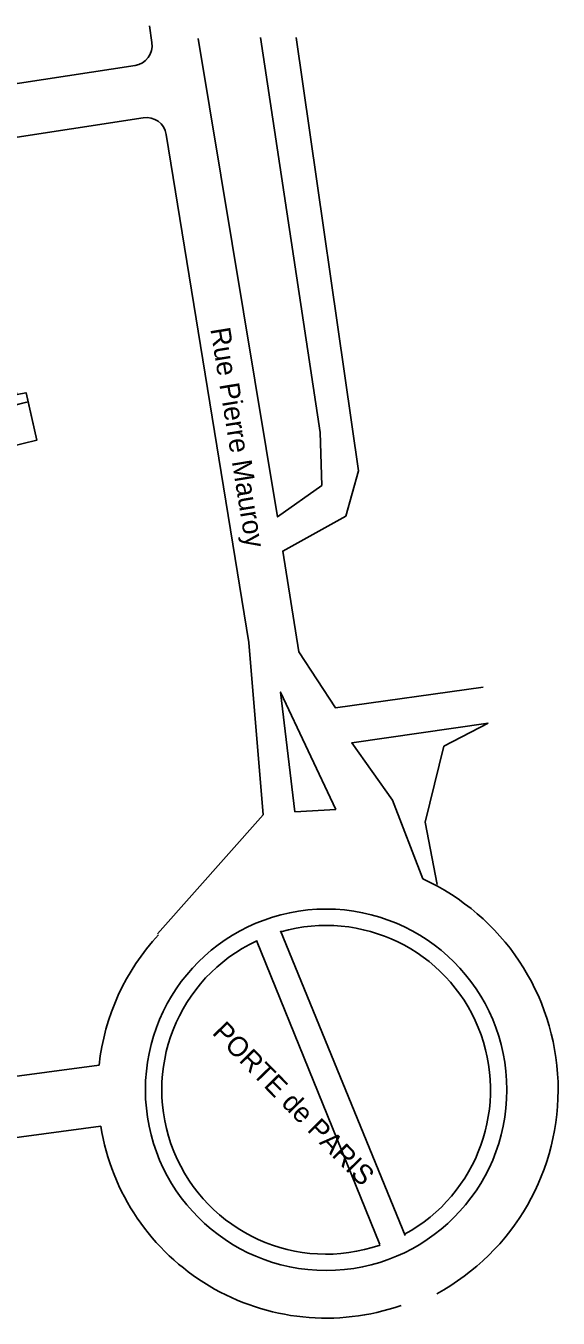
# Model space of a CAD drawing. Extents: x 704421 to 705059, y 7058908 to 7059523.
# Drawn here: x 704581.3 to 704661.8, y 7058918.9 to 7059114.3 of the extents above; entities that cross this region are included whole.
import ezdxf

# ---------------------------------------------------------------- set-up
doc = ezdxf.new("R2010")
doc.units = 0
for name, color, linetype in [('DH_HACHURE-MOTIF', 7, 'Continuous'), ('DH_TEXTE', 7, 'Continuous'), ('GO_MUR_EXTERIEUR', 7, 'Continuous'), ('IMM_LIMITE PHYSIQUE', 7, 'Continuous'), ('SID_POLYLIGNES_IMMEUBLE', 7, 'Continuous'), ('VOIRIE_ROUTE', 7, 'Continuous')]:
    doc.layers.add(name, color=color, linetype=linetype)

msp = doc.modelspace()

# ---------------------------------------------------------------- linework, layer by layer
at = {"layer": 'DH_HACHURE-MOTIF'}
msp.add_lwpolyline([(704564.85, 7059044.01), (704565.09, 7059042.95), (704579.84, 7059046.44), (704578.84, 7059050.66), (704582.98, 7059051.69), (704581.66, 7059057.48), (704581.22, 7059057.37), (704557.88, 7059051.53), (704560.06, 7059042.8), (704564.85, 7059044.01)], dxfattribs=at)
at = {"layer": 'GO_MUR_EXTERIEUR'}
for p, q in [((704557.88, 7059051.53), (704581.66, 7059057.48)), ((704581.66, 7059057.48), (704582.98, 7059051.69)), ((704582.98, 7059051.69), (704578.84, 7059050.66))]:
    msp.add_line(p, q, dxfattribs=at)
at = {"layer": 'IMM_LIMITE PHYSIQUE'}
msp.add_line((704582.5, 7059052.18), (704582.5, 7059052.18), dxfattribs=at)
msp.add_lwpolyline([(704578.99, 7059062.63), (704579.94, 7059058.58), (704581.34, 7059058.85), (704581.66, 7059057.48)], dxfattribs=at)
at = {"layer": 'SID_POLYLIGNES_IMMEUBLE'}
msp.add_line((704582.98, 7059051.69), (704578.84, 7059050.66), dxfattribs=at)
msp.add_lwpolyline([(704578.55, 7059067.1), (704579.45, 7059063.26), (704578.88, 7059063.11), (704579.94, 7059058.58), (704581.34, 7059058.85), (704582.98, 7059051.69)], dxfattribs=at)
at = {"layer": 'VOIRIE_ROUTE'}
for p, q in [((704617.16, 7058995.05), (704601.2, 7058977.03)), ((704628.17, 7058995.85), (704621.98, 7058995.48)), ((704619.81, 7058977.5), (704638.64, 7058931.4)), ((704616.19, 7058976.02), (704634.84, 7058930.03))]:
    msp.add_line(p, q, dxfattribs=at)
for points in [[(704600.36, 7059111.8), (704599.98, 7059114.34)], [(704607.38, 7059112.42), (704619.37, 7059040.08), (704626.07, 7059044.85), (704625.81, 7059052.84), (704616.79, 7059112.55)], [(704622.2, 7059112.55), (704631.61, 7059047.04), (704629.68, 7059040.21), (704620.14, 7059034.92), (704622.59, 7059019.7), (704628.13, 7059011.19), (704650.44, 7059014.32)], [(704439.21, 7059062.29), (704466.43, 7059084.66), (704472.47, 7059087.95), (704480.92, 7059090.49), (704597.81, 7059108.33)], [(704599.06, 7059100.45), (704481.77, 7059082.41), (704472.42, 7059078.45), (704444.83, 7059056.07)], [(704617.16, 7058995.05), (704615.01, 7059021.07), (704602.53, 7059097.92)], [(704621.98, 7058995.48), (704619.83, 7059013.58), (704628.17, 7058995.85)], [(704651.2, 7059008.87), (704630.58, 7059005.9), (704636.72, 7058997.22), (704641.32, 7058985.34)], [(704651.2, 7059008.87), (704644.5, 7059005.39), (704641.67, 7058993.91), (704643.52, 7058984.5)], [(704539.19, 7058950.05), (704592.38, 7058957.19)], [(704518.49, 7058920.73), (704534.04, 7058939.07), (704540.1, 7058940.88), (704592.62, 7058947.93)]]:
    msp.add_lwpolyline(points, dxfattribs=at)
msp.add_circle((704626.71, 7058953.45), 27.33, dxfattribs=at)
for centre, radius, start, end in [((704597.35, 7059111.34), 3.05, 278.6767, 8.6767), ((704599.52, 7059097.43), 3.05, 9.2218, 98.7403), ((704626.71, 7058953.45), 35.08, 298.459, 65.3951), ((704626.71, 7058953.45), 34.53, 137.2612, 173.7773), ((704626.71, 7058953.45), 24.85, 298.459, 105.9703), ((704626.71, 7058953.45), 24.85, 115.0132, 289.1455), ((704626.71, 7058953.45), 34.53, 189.1939, 289.1455)]:
    msp.add_arc(centre, radius, start, end, dxfattribs=at)

# ---------------------------------------------------------------- texts
at = {"layer": 'DH_TEXTE'}
for s, rotation, p in [('Rue Pierre Mauroy', 279.2071, (704609.19, 7059068.5)), ('PORTE de PARIS', 314.4253, (704609.34, 7058961.96))]:
    msp.add_text(s, height=3, rotation=rotation, dxfattribs=at).set_placement(p)

doc.saveas('drawing.dxf')
